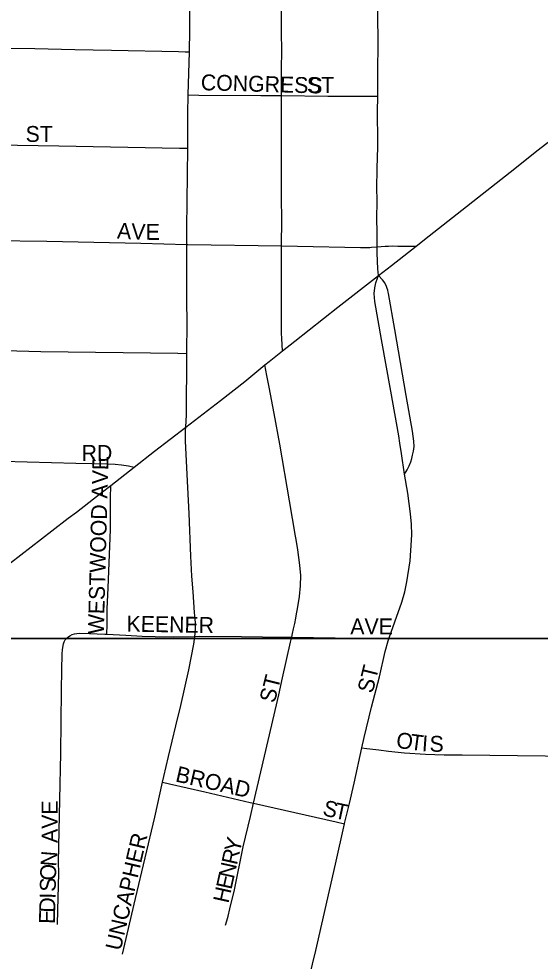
# Model space of a CAD drawing. Extents: x 1584893 to 1934202, y 663575 to 1091909.
# Drawn here: x 1788636 to 1790275, y 936183 to 939146 of the extents above; entities that cross this region are included whole.
import ezdxf

# ---------------------------------------------------------------- set-up
doc = ezdxf.new("R2010")
doc.units = 0
for name, color, linetype in [('GM_X_City_Street', 7, 'Continuous'), ('GM_X_City_Street_Text', 7, 'Continuous'), ('GM_X_Section', 7, 'Continuous'), ('GM_X_State_Route', 7, 'Continuous')]:
    doc.layers.add(name, color=color, linetype=linetype)

msp = doc.modelspace()

# ---------------------------------------------------------------- linework, layer by layer
at = {"layer": 'GM_X_City_Street'}
for points in [[(1789461.4, 938905.2), (1789461.5, 938974.7), (1789461.8, 939003.6), (1789462.1, 939031.1), (1789462, 939049.1), (1789461.3, 939101.3), (1789461.5, 939134.2), (1789461.7, 939216.4), (1789463.3, 939347.6), (1789464.5, 939511.7), (1789465, 939610.2), (1789464.9, 939641.8), (1789466.5, 939724), (1789466.5, 939755), (1789466.5, 939789.3), (1789467, 939817.1), (1789467.4, 939835.6), (1789467.4, 939851), (1789467.5, 939852.9)], [(1789763.8, 938903), (1789764.1, 938948.4), (1789764.3, 938967.7), (1789764.5, 939016.7), (1789765, 939033.1), (1789764.9, 939082.5), (1789764.7, 939148.1), (1789764.7, 939156.5), (1789764.9, 939189.4), (1789765.5, 939288), (1789764.7, 939320.6), (1789763.8, 939353.1), (1789765.3, 939484.5), (1789764.7, 939497.1), (1789764, 939514.7), (1789762.9, 939562.8), (1789764.6, 939841.8), (1789764.6, 939848.7)], [(1789172, 939042.8), (1789173.7, 939110.3), (1789173.6, 939162.5), (1789173, 939208.5), (1789172.8, 939339.9), (1789173.3, 939379.6)], [(1788555.1, 939053.8), (1788685.5, 939053.1), (1788811.4, 939050), (1788926.5, 939048.1), (1789137.6, 939043.5), (1789158.4, 939043), (1789172, 939042.8)], [(1789168.4, 938907.1), (1789172, 939042.8)], [(1789166.9, 938739.3), (1789167.1, 938750.3), (1789166.9, 938849), (1789168.4, 938907.1)], [(1789168.4, 938907.1), (1789201.6, 938906.9), (1789395.9, 938905.8), (1789461.4, 938905.2)], [(1789461.3, 938432.3), (1789461.4, 938436.3), (1789462.2, 938510.8), (1789462.5, 938538.1), (1789461.9, 938559.3), (1789461.8, 938580.9), (1789461.3, 938602.5), (1789460.9, 938623.9), (1789460.9, 938652.9), (1789460.9, 938678.5), (1789460.9, 938714.9), (1789460.9, 938762.3), (1789461.3, 938810.3), (1789461.7, 938843.8), (1789461.4, 938876.2), (1789461.4, 938905.2)], [(1789461.4, 938905.2), (1789606.6, 938903.5), (1789731.3, 938903.1), (1789763.8, 938903)], [(1789762.4, 938429.1), (1789762, 938480.2), (1789761.5, 938512.9), (1789762.2, 938578.6), (1789761.5, 938611.6), (1789761.9, 938677.1), (1789764, 938742.9), (1789764.5, 938775.8), (1789764.2, 938795.5), (1789763.7, 938820.5), (1789763.6, 938853.5), (1789763.8, 938903)], [(1788554.4, 938750.6), (1788564.9, 938750.5), (1788760.9, 938747.5), (1789140.8, 938739.8), (1789166.9, 938739.3)], [(1789163.8, 938436.5), (1789163.7, 938438.9), (1789163.5, 938463.2), (1789163.7, 938487.9), (1789166.9, 938739.3)], [(1788553.5, 938449.6), (1788723.6, 938446.8), (1789019.3, 938440.7), (1789163.8, 938436.5)], [(1789164, 938094.1), (1789165, 938192.6), (1789164.2, 938258.3), (1789163.8, 938436.5)], [(1789163.8, 938436.5), (1789166.8, 938436.4), (1789461.3, 938432.3)], [(1789465, 938102.5), (1789462.8, 938141.3), (1789461.8, 938157.6), (1789461.8, 938223.3), (1789461.6, 938280.2), (1789461.4, 938338.1), (1789460.9, 938387.1), (1789461.3, 938432.3)], [(1789461.3, 938432.3), (1789511.9, 938431.4), (1789709.4, 938427.5), (1789717.5, 938427.6), (1789730.1, 938427.6), (1789739.5, 938427.7), (1789744.6, 938428), (1789762.4, 938429.1)], [(1789766.8, 938339.1), (1789764.5, 938359.7), (1789763.4, 938384), (1789762.2, 938410.5), (1789762.4, 938429.1)], [(1789762.4, 938429.1), (1789787.7, 938431.1), (1789797.5, 938431.5), (1789810.3, 938432), (1789826.9, 938431.7), (1789868.1, 938431.4), (1789884.5, 938431.3)], [(1789848.4, 937714.2), (1789838.2, 937779.6), (1789833.4, 937811.5), (1789830, 937835), (1789804.6, 937974.9), (1789775.8, 938138.1), (1789755.1, 938257.7), (1789753, 938282.7), (1789754.6, 938300.1), (1789758.1, 938316.2), (1789763.6, 938330.6), (1789766.8, 938339.1)], [(1789848.4, 937714.2), (1789856.7, 937727.8), (1789863.2, 937740.4), (1789867.5, 937753), (1789871.2, 937764.1), (1789873.5, 937774.3), (1789876, 937787.1), (1789878.1, 937801.5), (1789877.2, 937817.9), (1789873.6, 937849.5), (1789853.1, 937961.5), (1789817.9, 938168.9), (1789797.5, 938282.2), (1789796.7, 938287.1), (1789795.2, 938293), (1789794.1, 938297.9), (1789791.7, 938304.8), (1789786, 938316.6), (1789778.5, 938325.7), (1789766.8, 938339.1)], [(1788552.4, 938104), (1788705.1, 938100.3), (1789135.5, 938094.4), (1789164, 938094.1)], [(1789160.4, 937861.8), (1789162.9, 937901.1), (1789162.6, 937912.6), (1789163, 937929.6), (1789163, 937962.3), (1789163.8, 938028.7), (1789163.6, 938061.3), (1789164, 938094.1)], [(1789493.6, 937201.2), (1789496.1, 937213.2), (1789499.2, 937227.5), (1789503, 937244.9), (1789506, 937261.4), (1789508.5, 937275), (1789510.7, 937285), (1789512.9, 937297.3), (1789518.4, 937329.7), (1789521.4, 937362.6), (1789521.7, 937395.6), (1789519.4, 937428.3), (1789512.8, 937476.7), (1789507.5, 937509.3), (1789505.8, 937519.5), (1789486.2, 937630.3), (1789456.1, 937808.3), (1789437.9, 937905), (1789422.2, 937987.9), (1789415.3, 938024.3), (1789408.9, 938057.9)], [(1789189.1, 937204.1), (1789190.2, 937212.9), (1789191.2, 937231.5), (1789190.8, 937246.4), (1789190.3, 937257.8), (1789187.9, 937279.1), (1789183.4, 937344.3), (1789179.2, 937393.7), (1789176.5, 937456.6), (1789171.1, 937590.2), (1789166.7, 937672.2), (1789159.3, 937818.2), (1789159.8, 937852.3), (1789160.4, 937861.8)], [(1788552, 937755.9), (1788585.1, 937755.1), (1788815.1, 937748.9), (1788915.3, 937746.5), (1788938.7, 937745.3), (1788958, 937743.8), (1788980.7, 937740.3), (1788997.8, 937736.2)], [(1789800, 937199.5), (1789805.8, 937217.1), (1789817.8, 937249.8), (1789839.8, 937311.9), (1789848.7, 937343.8), (1789855.5, 937376.1), (1789865.4, 937441.3), (1789868.1, 937474.2), (1789870.7, 937523.6), (1789869.8, 937556.8), (1789866.9, 937589.7), (1789858.4, 937654.9), (1789848.4, 937714.2)], [(1788912.6, 937210.9), (1788913, 937240.4), (1788913.7, 937290.3), (1788916, 937356.9), (1788923.3, 937539.8), (1788924.1, 937606.2), (1788924.2, 937639.3), (1788924.4, 937678.8)], [(1788757.6, 936297.5), (1788758.2, 936343.1), (1788759.8, 936419.7), (1788760.9, 936460.8), (1788760.7, 936493.5), (1788764.9, 936689.9), (1788767.6, 936837.2), (1788769.9, 937033.8), (1788770.8, 937098.4), (1788772, 937148.5), (1788773.3, 937163.1), (1788776, 937180.8), (1788777.7, 937186.7), (1788781.4, 937193.2), (1788788.3, 937201)], [(1788788.3, 937201), (1788796, 937206.3), (1788803, 937209.9), (1788810.3, 937212.4), (1788817.6, 937213.6), (1788826.6, 937214), (1788857.9, 937213.4), (1788906.4, 937211.2), (1788912.6, 937210.9)], [(1788912.6, 937210.9), (1788972.3, 937207.9), (1789023.2, 937204.7), (1789064.3, 937203.9), (1789121.7, 937202.8), (1789189.1, 937204.1)], [(1789087.2, 936745.9), (1789091, 936763.5), (1789106.2, 936826.1), (1789129.2, 936922.7), (1789144.9, 936987.1), (1789170.4, 937099.1), (1789185.9, 937179.8), (1789189.1, 937204.1)], [(1789189.1, 937204.1), (1789203.9, 937204.4), (1789335.4, 937203.8), (1789467.4, 937201.6), (1789493.6, 937201.2)], [(1789373.4, 936679.6), (1789419.1, 936876.4), (1789452.9, 937020.4), (1789464.9, 937073.4), (1789489.5, 937185.9), (1789492.9, 937198.6), (1789493.6, 937201.2)], [(1789493.6, 937201.2), (1789698.6, 937198.2), (1789764.9, 937199), (1789800, 937199.5)], [(1789714.2, 936853.3), (1789721.6, 936886.3), (1789744.7, 936981.8), (1789769.2, 937077.2), (1789787.5, 937156.9), (1789796.8, 937190.2), (1789800, 937199.5)], [(1789659.1, 936614.3), (1789659.4, 936615.9), (1789675.2, 936679), (1789689.5, 936742.8), (1789714.2, 936853.3)], [(1789714.2, 936853.3), (1789730.1, 936851.4), (1789767.3, 936847), (1789798.2, 936843.3), (1789847.6, 936838.3), (1789913.6, 936833.7), (1789972.6, 936831.7), (1790029.7, 936831.4), (1790377.8, 936827.8), (1790410.9, 936828.3), (1790437.9, 936828.7)], [(1788962, 936204.4), (1789002.9, 936380.2), (1789062.9, 936635.9), (1789087.2, 936745.9)], [(1789087.2, 936745.9), (1789109.4, 936740.8), (1789220.4, 936715.3), (1789363, 936681.9), (1789373.4, 936679.6)], [(1789285.4, 936295.3), (1789289.9, 936309.1), (1789294.1, 936324.6), (1789299.3, 936346.7), (1789313.3, 936407.4), (1789341.2, 936542.2), (1789363.6, 936638), (1789373.4, 936679.6)], [(1789373.4, 936679.6), (1789632.8, 936620.3), (1789659.1, 936614.3)], [(1789187.6, 934578.6), (1789241.7, 934810.6), (1789282.9, 935003.1), (1789322.6, 935178.9), (1789395.1, 935482), (1789447.1, 935705.6), (1789515.3, 935992.8), (1789569.2, 936216), (1789631.2, 936487.9), (1789659.1, 936614.3)]]:
    msp.add_lwpolyline(points, dxfattribs=at)
at = {"layer": 'GM_X_Section'}
for points in [[(1787878.9, 942509.8), (1793145.7, 942483.9), (1793117.6, 937197.1), (1787862.6, 937197)], [(1787862.6, 937197), (1793117.6, 937197.1), (1793087.2, 931880.4), (1787794.6, 931920.6)]]:
    msp.add_lwpolyline(points, close=True, dxfattribs=at)
at = {"layer": 'GM_X_State_Route'}
for points in [[(1789926.1, 938464.1), (1790180.3, 938664), (1790268.7, 938734.8), (1790456.4, 938878.8), (1790525.7, 938931.9), (1790578.3, 938971), (1790642.8, 939021), (1790705.5, 939069.4)], [(1789766.8, 938339.1), (1789807.2, 938370.6), (1789884.5, 938431.3), (1789926.1, 938464.1)], [(1788334.4, 937220.4), (1788361.7, 937241.5), (1788394.2, 937265.8), (1788410.1, 937278.2), (1788427, 937291), (1788555.8, 937392.6), (1788609.6, 937435.2), (1788738.9, 937536.5), (1788790.7, 937576.2), (1788816.8, 937595.1), (1788894.1, 937655.1), (1788924.4, 937678.8), (1788997.8, 937736.2), (1789062.5, 937786.8), (1789160.4, 937861.8), (1789270.1, 937945.7), (1789346.3, 938005.7), (1789408.9, 938057.9), (1789422.2, 938069), (1789465, 938102.5), (1789503, 938132.3), (1789638.9, 938239.8), (1789766.8, 938339.1)]]:
    msp.add_lwpolyline(points, dxfattribs=at)

# ---------------------------------------------------------------- texts
at = {"layer": 'GM_X_City_Street_Text'}
for s, rotation, p in [('CONGRESS', 358.4089, (1789207.3, 938922.1)), ('ST', 0, (1789541.3, 938913.3)), ('ST', 0, (1788656.9, 938759.3)), ('A', 356.7195, (1788943.5, 938455.7)), ('V', 357.831, (1788988.4, 938453.2)), ('E', 359.8075, (1789034.3, 938451.4)), ('RD', 0, (1788832.9, 937756.1)), ('WESTWOOD AVE', 88.4799, (1788902.7, 937210.3)), ('KEENER', 358.9936, (1788973.9, 937219.3)), ('AVE', 0, (1789677.7, 937210.5)), ('ST', 75.9734, (1789747.8, 937023)), ('ST', 75.9734, (1789439.8, 936992.2)), ('O', 352.349, (1789819.8, 936854.1)), ('T', 352.4105, (1789863.4, 936848.2)), ('I', 355.8546, (1789901.6, 936843.2)), ('S', 359.1163, (1789926.6, 936841.5)), ('BROAD', 347.0952, (1789125.4, 936748.3)), ('AVE', 90, (1788757.5, 936554.3)), ('S', 345.2745, (1789587.9, 936642.6)), ('T', 348.0528, (1789624.5, 936633)), ('UNCAPHER', 76.8917, (1788955.7, 936213.3)), ('Y', 76.0486, (1789329.6, 936521.3)), ('N', 85.3398, (1788753.3, 936479)), ('R', 77.5308, (1789321.1, 936483)), ('O', 88.5138, (1788752.2, 936435.7)), ('N', 77.5068, (1789311.6, 936440)), ('E', 77.5247, (1789304, 936405.7)), ('S', 88.5248, (1788751.3, 936400.5)), ('I', 88.4696, (1788750.7, 936378.5)), ('H', 77.5068, (1789294.5, 936362.7)), ('D', 88.5138, (1788749.6, 936334.5)), ('E', 88.5242, (1788748.7, 936299.3))]:
    msp.add_text(s, height=50, rotation=rotation, dxfattribs=at).set_placement(p)

doc.saveas('drawing.dxf')
